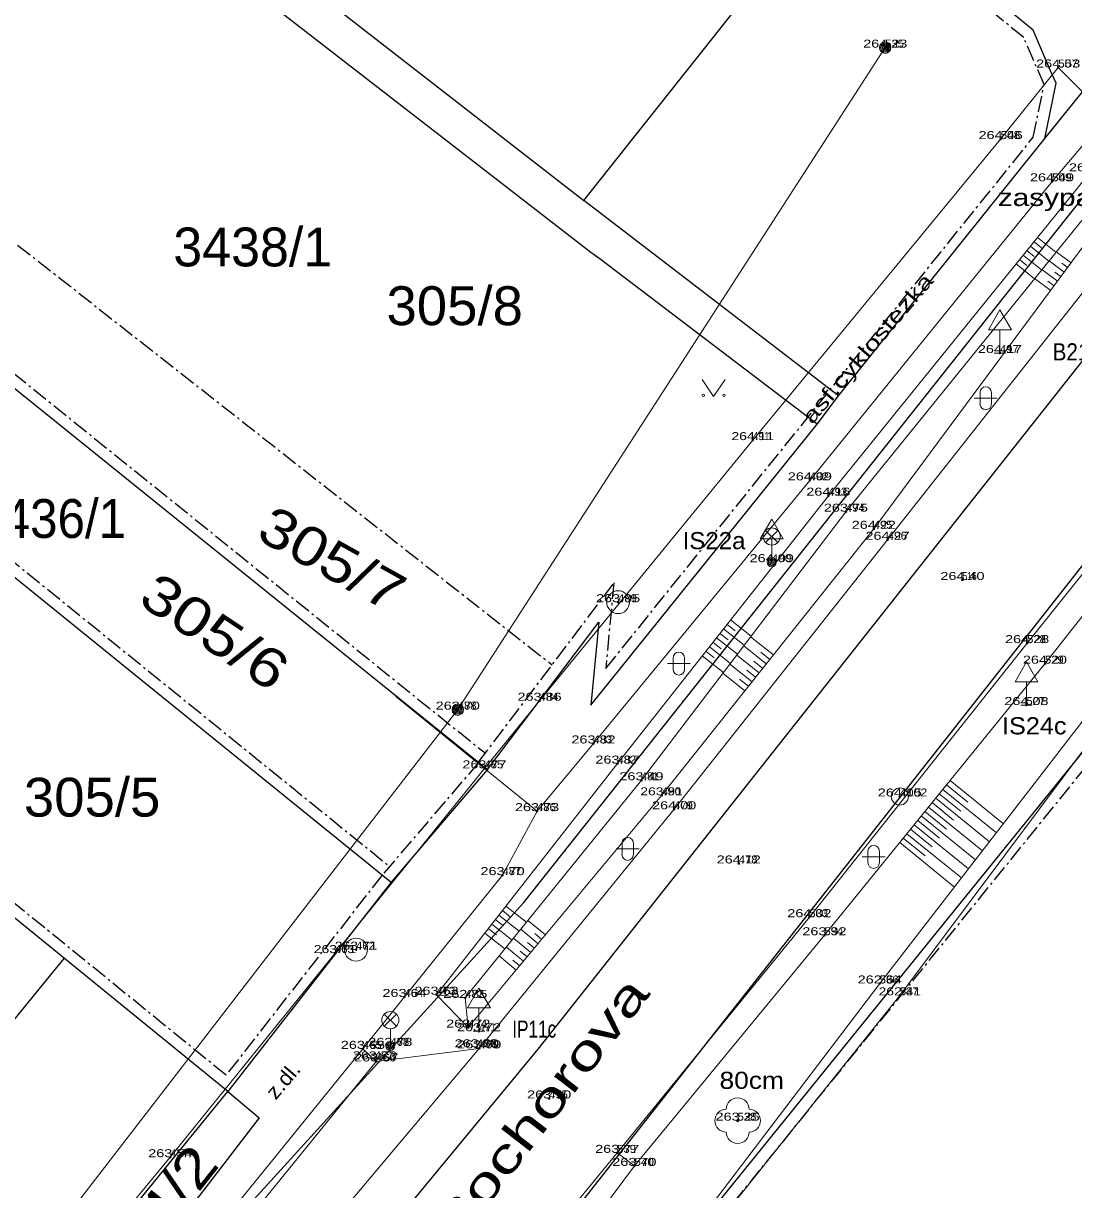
# Model space of a CAD drawing. Extents: x -568530 to -568223, y -1154101 to -1153740.
# Drawn here: x -568404.2 to -568358.2, y -1153886.3 to -1153835.3 of the extents above; entities that cross this region are included whole.
import ezdxf
from ezdxf.enums import TextEntityAlignment as Align

# ---------------------------------------------------------------- set-up
doc = ezdxf.new("R2010")
doc.units = 0
doc.header["$LTSCALE"] = 0.14
doc.header["$PDMODE"] = 32
doc.header["$PDSIZE"] = 0.07
doc.linetypes.add('DOT_DASHED', pattern=[7.7, 5, -1.2, 0.3, -1.2])
for name, color, linetype, lineweight in [('1', 7, 'Continuous', 25), ('10', 7, 'Continuous', 13), ('11', 7, 'Continuous', 13), ('12', 7, 'Continuous', 13), ('14', 7, 'Continuous', 13), ('15', 7, 'Continuous', 13), ('21', 7, 'Continuous', 13), ('22', 7, 'Continuous', 13), ('23', 7, 'Continuous', 13), ('25', 7, 'Continuous', 13), ('27', 7, 'Continuous', 13), ('33', 7, 'Continuous', 13), ('34', 7, 'Continuous', 13), ('36', 7, 'Continuous', 13), ('4', 7, 'Continuous', 25), ('42', 7, 'Continuous', 13), ('51', 7, 'Continuous', 13), ('6', 7, 'DOT_DASHED', 25), ('7', 7, 'Continuous', 13)]:
    doc.layers.add(name, color=color, linetype=linetype, lineweight=lineweight)
for name, color, linetype in [('13', 7, 'Continuous'), ('18', 7, 'Continuous'), ('20', 7, 'Continuous'), ('40', 7, 'Continuous'), ('49', 7, 'Continuous')]:
    doc.layers.add(name, color=color, linetype=linetype)

msp = doc.modelspace()

# ---------------------------------------------------------------- linework, layer by layer
at = {"layer": '1'}
for points in [[(-568412.56, -1153907.8), (-568411.98, -1153907.12), (-568411.65, -1153906.73), (-568402.04, -1153895.41), (-568393.94, -1153886.59), (-568382.28, -1153873.78), (-568334.11, -1153813.06), (-568281.93, -1153748.16)], [(-568397.85, -1153916.62), (-568348.36, -1153855.52), (-568306.73, -1153803.52), (-568266.23, -1153754.08)], [(-568359.48, -1153840.35), (-568353.42, -1153832.84), (-568366.2, -1153822.48), (-568392.31, -1153801.22), (-568392.76, -1153800.31), (-568393.76, -1153795.28)], [(-568383.87, -1153867.96), (-568379, -1153861.51), (-568379.35, -1153865.15), (-568369.44, -1153852.85), (-568368.51, -1153851.61), (-568359.48, -1153840.35), (-568358.98, -1153837.93), (-568359.22, -1153837.4), (-568359.99, -1153835.62), (-568366.98, -1153829.88), (-568367.36, -1153829.57), (-568368.31, -1153828.79), (-568387.83, -1153813.79), (-568393.04, -1153809.23)], [(-568426.4, -1153841.88), (-568423.86, -1153835.73), (-568423.37, -1153836.16), (-568412.01, -1153845.3), (-568383.87, -1153867.96), (-568388.09, -1153872.89)], [(-568431.55, -1153854.18), (-568426.4, -1153841.88), (-568388.09, -1153872.89), (-568395.23, -1153882.04)], [(-568395.23, -1153882.04), (-568406.86, -1153872.6), (-568418.87, -1153863.43), (-568431.55, -1153854.18), (-568440.41, -1153875.53)], [(-568413.73, -1153908), (-568415.28, -1153906.83), (-568404.79, -1153893.8), (-568402.87, -1153891.42), (-568401.2, -1153889.36), (-568395.23, -1153882.04), (-568393.86, -1153883.19), (-568402.8, -1153894.84), (-568404.79, -1153893.8)]]:
    msp.add_lwpolyline(points, dxfattribs=at)
msp.add_lwpolyline([(-568379.65, -1153843.07), (-568372.58, -1153834.15), (-568388.26, -1153822.12), (-568391.64, -1153826.52), (-568389.96, -1153827.98), (-568393.38, -1153832.39)], close=True, dxfattribs=at)
at = {"layer": '10'}
for points in [[(-568358.89, -1153837.25), (-568356.74, -1153839.4), (-568355.85, -1153842.56), (-568355.35, -1153843.15), (-568355.9, -1153844.67)], [(-568341.41, -1153838.94), (-568349.83, -1153849.41), (-568360.25, -1153862.43), (-568369.78, -1153874.42), (-568378.19, -1153884.73), (-568386.01, -1153894.27), (-568392.67, -1153902.27), (-568398.22, -1153909.37), (-568401.79, -1153914.15), (-568403.6, -1153916.28)], [(-568355.9, -1153844.67), (-568366.36, -1153857.91), (-568375.7, -1153869.7), (-568384.23, -1153880.16)], [(-568384.23, -1153880.16), (-568392.01, -1153889.4), (-568398.35, -1153897.64), (-568404.75, -1153905.51), (-568410.43, -1153912.49)]]:
    msp.add_lwpolyline(points, dxfattribs=at)
at = {"layer": '11'}
for p, q in [((-568381.7, -1153869.78), (-568384, -1153867.91)), ((-568388.74, -1153880.73), (-568389.32, -1153880.18)), ((-568378.19, -1153884.73), (-568377.44, -1153885.3))]:
    msp.add_line(p, q, dxfattribs=at)
for points in [[(-568358.89, -1153837.25), (-568361.41, -1153840.38), (-568372.26, -1153853.55), (-568381.59, -1153864.95), (-568384, -1153867.91)], [(-568381.7, -1153869.78), (-568379.23, -1153866.82), (-568369.76, -1153855.31), (-568359.16, -1153842.23), (-568356.74, -1153839.4)], [(-568381.7, -1153869.78), (-568383.21, -1153872.58), (-568387.5, -1153877.91), (-568389.32, -1153880.18), (-568394.71, -1153886.81), (-568401.41, -1153895.07), (-568405.07, -1153899.62), (-568408.29, -1153903.1), (-568410.38, -1153905.27)], [(-568384.23, -1153880.16), (-568388.74, -1153880.73), (-568394.35, -1153887.63), (-568400.75, -1153895.57), (-568404.48, -1153900.2), (-568404.75, -1153905.51)], [(-568377.44, -1153885.3), (-568384.74, -1153895.11), (-568391.27, -1153903.31), (-568397.56, -1153910.73)]]:
    msp.add_lwpolyline(points, dxfattribs=at)
for p in [(-568366.46, -1153836.38), (-568358.89, -1153837.25), (-568361.41, -1153840.38), (-568359.16, -1153842.23), (-568361.44, -1153849.74), (-568372.26, -1153853.55), (-568369.76, -1153855.31), (-568368.95, -1153855.98), (-568368.18, -1153856.68), (-568366.96, -1153857.43), (-568366.36, -1153857.91), (-568371.43, -1153858.89), (-568363.08, -1153859.67), (-568378.15, -1153860.64), (-568360.25, -1153862.43), (-568359.47, -1153863.33), (-568385.17, -1153865.34), (-568381.59, -1153864.95), (-568360.28, -1153865.14), (-568379.23, -1153866.82), (-568384, -1153867.91), (-568378.18, -1153867.7), (-568377.13, -1153868.43), (-568376.25, -1153869.09), (-568381.7, -1153869.78), (-568375.7, -1153869.7), (-568372.87, -1153872.07), (-568383.21, -1153872.58), (-568369.78, -1153874.42), (-568369.12, -1153875.21), (-568390.54, -1153875.99), (-568389.62, -1153875.84), (-568366.7, -1153877.32), (-568387.5, -1153877.91), (-568386.1, -1153877.81), (-568384.84, -1153877.95), (-568365.82, -1153877.84), (-568384.71, -1153879.25), (-568384.24, -1153879.41), (-568389.32, -1153880.18), (-568388.12, -1153880.05), (-568384.34, -1153880.11), (-568384.23, -1153880.16), (-568388.8, -1153880.64), (-568388.74, -1153880.73), (-568381.17, -1153882.35), (-568372.92, -1153883.32), (-568378.19, -1153884.73), (-568397.75, -1153884.92), (-568377.44, -1153885.3)]:
    msp.add_point(p, dxfattribs=at)
at = {"layer": '14'}
for points in [[(-568340.75, -1153839.71), (-568349.18, -1153850.27), (-568359.47, -1153863.33), (-568369.12, -1153875.21), (-568377.44, -1153885.3)], [(-568395.11, -1153912.31), (-568389.39, -1153905.01), (-568382.04, -1153896.57), (-568374.93, -1153888.14), (-568366.7, -1153877.32), (-568357.21, -1153865.06), (-568347.39, -1153851.22), (-568338.19, -1153841.21)], [(-568357.45, -1153841.79), (-568368.95, -1153855.98), (-568378.18, -1153867.7), (-568386.1, -1153877.81), (-568384.71, -1153879.25), (-568384.84, -1153877.95), (-568386.1, -1153877.81)], [(-568384.84, -1153877.95), (-568377.13, -1153868.43), (-568368.18, -1153856.68), (-568356.81, -1153842.64)], [(-568384.71, -1153879.25), (-568376.25, -1153869.09), (-568366.96, -1153857.43), (-568356.13, -1153842.84)]]:
    msp.add_lwpolyline(points, dxfattribs=at)
at = {"layer": '15'}
for p, q in [((-568359.948, -1153844.873), (-568359.627, -1153845.133)), ((-568359.791, -1153844.679), (-568358.988, -1153845.329)), ((-568360.421, -1153845.455), (-568359.617, -1153846.106)), ((-568360.263, -1153845.261), (-568359.942, -1153845.522)), ((-568360.106, -1153845.067), (-568359.303, -1153845.718)), ((-568358.325, -1153845.797), (-568358.975, -1153845.314)), ((-568360.735, -1153845.844), (-568359.932, -1153846.495)), ((-568360.578, -1153845.65), (-568360.257, -1153845.91)), ((-568358.623, -1153846.198), (-568359.29, -1153845.703)), ((-568358.474, -1153845.997), (-568358.737, -1153845.802)), ((-568359.219, -1153847.001), (-568359.92, -1153846.48)), ((-568358.921, -1153846.6), (-568359.605, -1153846.092)), ((-568358.772, -1153846.399), (-568359.042, -1153846.198)), ((-568359.07, -1153846.8), (-568359.347, -1153846.595)), ((-568373.538, -1153861.806), (-568372.63, -1153862.522)), ((-568373.384, -1153861.61), (-568373.021, -1153861.895)), ((-568373.229, -1153861.413), (-568372.327, -1153862.124)), ((-568373.848, -1153862.199), (-568372.933, -1153862.92)), ((-568373.693, -1153862.003), (-568373.328, -1153862.29)), ((-568371.356, -1153862.947), (-568372.35, -1153862.155)), ((-568374.312, -1153862.788), (-568373.942, -1153863.079)), ((-568374.157, -1153862.592), (-568373.236, -1153863.317)), ((-568374.002, -1153862.395), (-568373.635, -1153862.685)), ((-568371.667, -1153863.338), (-568372.653, -1153862.553)), ((-568371.512, -1153863.143), (-568371.908, -1153862.827)), ((-568374.466, -1153862.985), (-568373.539, -1153863.715)), ((-568372.291, -1153864.12), (-568373.259, -1153863.349)), ((-568371.979, -1153863.729), (-568372.956, -1153862.951)), ((-568371.823, -1153863.534), (-568372.216, -1153863.221)), ((-568372.602, -1153864.512), (-568373.562, -1153863.746)), ((-568372.135, -1153863.925), (-568372.524, -1153863.615)), ((-568372.446, -1153864.316), (-568372.832, -1153864.009)), ((-568363.62, -1153868.439), (-568361.29, -1153870.331)), ((-568363.935, -1153868.827), (-568361.596, -1153870.727)), ((-568363.778, -1153868.633), (-568362.844, -1153869.391)), ((-568364.408, -1153869.409), (-568363.467, -1153870.173)), ((-568364.25, -1153869.215), (-568361.903, -1153871.122)), ((-568364.093, -1153869.021), (-568363.155, -1153869.782)), ((-568364.881, -1153869.991), (-568362.515, -1153871.913)), ((-568364.723, -1153869.797), (-568363.779, -1153870.565)), ((-568364.566, -1153869.603), (-568362.209, -1153871.518)), ((-568365.196, -1153870.379), (-568362.821, -1153872.309)), ((-568365.039, -1153870.185), (-568364.09, -1153870.956)), ((-568365.669, -1153870.962), (-568364.713, -1153871.738)), ((-568365.511, -1153870.767), (-568363.127, -1153872.704)), ((-568365.354, -1153870.573), (-568364.402, -1153871.347)), ((-568365.827, -1153871.156), (-568363.433, -1153873.1)), ((-568383.064, -1153873.935), (-568382.161, -1153874.642)), ((-568383.527, -1153874.525), (-568383.169, -1153874.805)), ((-568383.372, -1153874.328), (-568382.476, -1153875.031)), ((-568383.218, -1153874.131), (-568382.858, -1153874.413)), ((-568381.335, -1153875.197), (-568382.097, -1153874.563)), ((-568383.835, -1153874.919), (-568383.48, -1153875.197)), ((-568383.681, -1153874.722), (-568382.791, -1153875.419)), ((-568381.655, -1153875.581), (-568382.412, -1153874.951)), ((-568383.989, -1153875.116), (-568383.105, -1153875.808)), ((-568381.975, -1153875.966), (-568382.726, -1153875.34)), ((-568381.815, -1153875.773), (-568382.117, -1153875.522)), ((-568381.495, -1153875.389), (-568381.799, -1153875.136)), ((-568382.615, -1153876.734), (-568383.356, -1153876.117)), ((-568382.295, -1153876.35), (-568383.041, -1153875.729)), ((-568382.135, -1153876.158), (-568382.435, -1153875.908)), ((-568382.455, -1153876.542), (-568382.752, -1153876.294))]:
    msp.add_line(p, q, dxfattribs=at)
at = {"layer": '21'}
for radius in [0.375, 0.05]:
    msp.add_circle((-568365.82, -1153869.14), radius, dxfattribs=at)
at = {"layer": '22'}
msp.add_circle((-568372.92, -1153883.32), 0.05, dxfattribs=at)
for centre, start, end in [((-568372.92, -1153882.82), 0, 180), ((-568373.42, -1153883.32), 90, 270), ((-568372.42, -1153883.32), 270, 90), ((-568372.92, -1153883.82), 180, 0)]:
    msp.add_arc(centre, 0.5, start, end, dxfattribs=at)
at = {"layer": '23'}
msp.add_lwpolyline([(-568354.04, -1153929.41), (-568364.61, -1153923.44), (-568379.16, -1153915.86), (-568390.37, -1153909.46), (-568387.81, -1153906.15), (-568381.36, -1153897.16), (-568374.28, -1153888.42), (-568365.82, -1153877.84), (-568356.68, -1153865.62), (-568346.38, -1153852.31), (-568338.19, -1153841.21)], dxfattribs=at)
at = {"layer": '25'}
for centre, radius in [((-568366.46, -1153836.38), 0.25), ((-568366.46, -1153836.38), 0.2), ((-568366.46, -1153836.38), 0.15), ((-568366.46, -1153836.38), 0.1), ((-568366.46, -1153836.38), 0.05), ((-568385.17, -1153865.34), 0.25), ((-568385.17, -1153865.34), 0.2), ((-568385.17, -1153865.34), 0.15), ((-568385.17, -1153865.34), 0.1), ((-568385.17, -1153865.34), 0.05)]:
    msp.add_circle(centre, radius, dxfattribs=at)
at = {"layer": '27'}
for centre in [(-568378.15, -1153860.64), (-568389.62, -1153875.84)]:
    msp.add_circle(centre, 0.5, dxfattribs=at)
at = {"layer": '33'}
for p, q in [((-568371.695, -1153858.03), (-568371.165, -1153857.5)), ((-568371.695, -1153857.5), (-568371.165, -1153858.03)), ((-568371.43, -1153858.14), (-568371.43, -1153858.89)), ((-568388.385, -1153879.19), (-568387.855, -1153878.66)), ((-568388.385, -1153878.66), (-568387.855, -1153879.19)), ((-568388.12, -1153879.3), (-568388.12, -1153880.05))]:
    msp.add_line(p, q, dxfattribs=at)
for centre, radius in [((-568371.43, -1153857.765), 0.375), ((-568371.43, -1153858.89), 0.2), ((-568371.43, -1153858.89), 0.1445), ((-568371.43, -1153858.89), 0.0876), ((-568388.12, -1153878.925), 0.375), ((-568388.12, -1153880.05), 0.2), ((-568388.12, -1153880.05), 0.1445), ((-568388.12, -1153880.05), 0.0876)]:
    msp.add_circle(centre, radius, dxfattribs=at)
at = {"layer": '34'}
for p, q in [((-568361.44, -1153848.722), (-568361.44, -1153849.74)), ((-568361.69, -1153849.74), (-568361.19, -1153849.74)), ((-568371.43, -1153857.872), (-568371.43, -1153858.89)), ((-568360.28, -1153864.122), (-568360.28, -1153865.14)), ((-568360.53, -1153865.14), (-568360.03, -1153865.14)), ((-568384.24, -1153878.392), (-568384.24, -1153879.41)), ((-568384.49, -1153879.41), (-568383.99, -1153879.41))]:
    msp.add_line(p, q, dxfattribs=at)
for points in [[(-568361.94, -1153848.722), (-568360.94, -1153848.722), (-568361.44, -1153847.856)], [(-568371.93, -1153857.872), (-568370.93, -1153857.872), (-568371.43, -1153857.006)], [(-568360.78, -1153864.122), (-568359.78, -1153864.122), (-568360.28, -1153863.256)], [(-568384.74, -1153878.392), (-568383.74, -1153878.392), (-568384.24, -1153877.526)]]:
    msp.add_lwpolyline(points, close=True, dxfattribs=at)
at = {"layer": '36'}
for p, q in [((-568362.312, -1153851.467), (-568362.312, -1153851.967)), ((-568361.812, -1153851.467), (-568361.812, -1153851.967)), ((-568362.562, -1153851.717), (-568361.562, -1153851.717)), ((-568375.992, -1153863.325), (-568374.992, -1153863.325)), ((-568375.742, -1153863.075), (-568375.742, -1153863.575)), ((-568375.242, -1153863.075), (-568375.242, -1153863.575)), ((-568378.231, -1153871.431), (-568377.231, -1153871.431)), ((-568377.981, -1153871.181), (-568377.981, -1153871.681)), ((-568377.481, -1153871.181), (-568377.481, -1153871.681)), ((-568367.465, -1153871.782), (-568366.465, -1153871.782)), ((-568367.215, -1153871.532), (-568367.215, -1153872.032)), ((-568366.715, -1153871.532), (-568366.715, -1153872.032))]:
    msp.add_line(p, q, dxfattribs=at)
msp.add_lwpolyline([(-568374.47, -1153850.893), (-568373.97, -1153851.643), (-568373.47, -1153850.893)], dxfattribs=at)
for centre in [(-568374.4206, -1153851.5927), (-568373.5212, -1153851.5927)]:
    msp.add_circle(centre, 0.05, dxfattribs=at)
for centre, start, end in [((-568362.0622, -1153851.4692), 0, 180), ((-568362.0622, -1153851.9692), 180, 0), ((-568375.4922, -1153863.0771), 0, 180), ((-568375.4922, -1153863.5771), 180, 0), ((-568377.7315, -1153871.1828), 0, 180), ((-568366.9648, -1153871.534), 0, 180), ((-568377.7315, -1153871.6828), 180, 0), ((-568366.9648, -1153872.034), 180, 0)]:
    msp.add_arc(centre, 0.25, start, end, dxfattribs=at)
at = {"layer": '4'}
msp.add_line((-568368.51, -1153851.61), (-568379.65, -1153843.07), dxfattribs=at)
for points in [[(-568271.05, -1153741.89), (-568310.68, -1153791.16), (-568343.12, -1153831.47), (-568381.67, -1153880.2), (-568407.5, -1153911.44)], [(-568401.59, -1153914.63), (-568397.99, -1153910.05), (-568332.4, -1153826.72), (-568306.48, -1153794.28), (-568270.78, -1153751.53)], [(-568369.44, -1153852.85), (-568378.94, -1153845.64), (-568379.34, -1153845.34), (-568413.29, -1153819.07)], [(-568422.9, -1153878.41), (-568413.58, -1153883.34), (-568414.1, -1153884.23), (-568410.52, -1153886.17), (-568402.39, -1153876.23)]]:
    msp.add_lwpolyline(points, dxfattribs=at)
at = {"layer": '51'}
msp.add_lwpolyline([(-568408.38, -1153895.39), (-568385.17, -1153865.34), (-568366.46, -1153836.38)], dxfattribs=at)
at = {"layer": '6'}
for p, q in [((-568360.4, -1153835.94), (-568367.3, -1153830.27)), ((-568359.51, -1153838), (-568360.4, -1153835.94)), ((-568413.37, -1153838), (-568381.04, -1153863.38)), ((-568359.98, -1153840.3), (-568359.51, -1153838.01)), ((-568378.69, -1153863.54), (-568359.98, -1153840.3)), ((-568426.09, -1153841.49), (-568388.15, -1153872.2)), ((-568411.7, -1153844.91), (-568383.96, -1153867.25)), ((-568390.25, -1153908.12), (-568347.97, -1153855.84)), ((-568384.27, -1153867.66), (-568378.34, -1153859.81)), ((-568378.34, -1153859.8), (-568378.69, -1153863.54)), ((-568384.25, -1153867.64), (-568388.47, -1153872.57)), ((-568395.31, -1153881.33), (-568406.55, -1153872.21)), ((-568388.48, -1153872.58), (-568395.31, -1153881.33))]:
    msp.add_line(p, q, dxfattribs=at)
at = {"layer": '7'}
msp.add_line((-568387.886, -1153864.764), (-568384, -1153867.91), dxfattribs=at)
msp.add_lwpolyline([(-568384, -1153867.91), (-568390.54, -1153875.99), (-568397.75, -1153884.92), (-568401.83, -1153889.84)], dxfattribs=at)

# ---------------------------------------------------------------- texts
at = {"layer": '12'}
for s, width, p in [('264.23', 1.35, (-568366.46, -1153836.38)), ('264.53', 1.35, (-568358.89, -1153837.25)), ('264.46', 1.35, (-568361.41, -1153840.38)), ('264.49', 1.35, (-568359.16, -1153842.23)), ('264.49', 1.35, (-568357.45, -1153841.79)), ('264.17', 1.35, (-568361.44, -1153849.74)), ('264.11', 1.3, (-568372.26, -1153853.55)), ('264.09', 1.35, (-568369.76, -1153855.31)), ('264.16', 1.35, (-568368.95, -1153855.98)), ('263.75', 1.35, (-568368.1805, -1153856.68)), ('264.22', 1.35, (-568366.96, -1153857.43)), ('264.27', 1.35, (-568366.36, -1153857.91)), ('264.09', 1.35, (-568371.43, -1153858.89)), ('264.40', 1.35, (-568363.0795, -1153859.67)), ('263.95', 1.35, (-568378.1505, -1153860.64)), ('264.28', 1.35, (-568360.25, -1153862.43)), ('264.20', 1.35, (-568359.4695, -1153863.33)), ('263.86', 1.35, (-568381.59, -1153864.95)), ('264.08', 1.35, (-568360.28, -1153865.14)), ('263.70', 1.35, (-568385.1695, -1153865.34)), ('263.82', 1.35, (-568379.23, -1153866.82)), ('263.87', 1.35, (-568378.18, -1153867.7)), ('263.77', 1.35, (-568384, -1153867.91)), ('263.49', 1.35, (-568377.13, -1153868.43)), ('263.91', 1.3, (-568376.25, -1153869.09)), ('263.73', 1.35, (-568381.7, -1153869.78)), ('264.00', 1.35, (-568375.6995, -1153869.7)), ('264.12', 1.35, (-568372.87, -1153872.07)), ('263.70', 1.35, (-568383.2095, -1153872.58)), ('264.02', 1.35, (-568369.78, -1153874.42)), ('263.92', 1.35, (-568369.12, -1153875.21)), ('263.71', 1.3, (-568389.62, -1153875.84)), ('263.71', 1.3, (-568390.54, -1153875.99)), ('262.64', 1.35, (-568366.7, -1153877.32)), ('263.64', 1.35, (-568387.5, -1153877.91)), ('263.63', 1.35, (-568386.1, -1153877.81)), ('262.85', 1.35, (-568384.8405, -1153877.95)), ('262.41', 1.3, (-568365.82, -1153877.84)), ('263.72', 1.35, (-568384.71, -1153879.25)), ('263.72', 1.35, (-568384.24, -1153879.41)), ('263.65', 1.35, (-568389.3205, -1153880.18)), ('263.78', 1.35, (-568388.12, -1153880.05)), ('263.80', 1.35, (-568384.3395, -1153880.11)), ('263.79', 1.35, (-568384.23, -1153880.16)), ('263.73', 1.35, (-568388.8, -1153880.64)), ('263.67', 1.35, (-568388.74, -1153880.73)), ('263.90', 1.35, (-568381.1695, -1153882.35)), ('263.25', 1.35, (-568372.9205, -1153883.32)), ('263.54', 1.35, (-568397.75, -1153884.92)), ('263.77', 1.35, (-568378.19, -1153884.73)), ('263.70', 1.35, (-568377.4395, -1153885.3))]:
    msp.add_text(s, height=0.35, dxfattribs=dict(at, width=width)).set_placement(p, align=Align.CENTER)
at = {"layer": '13'}
for s, width, p in [('535', 1.05, (-568366.46, -1153836.38)), ('507', 1.1, (-568358.89, -1153837.25)), ('508', 1.1, (-568361.41, -1153840.38)), ('509', 1.1, (-568359.16, -1153842.23)), ('497', 1.05, (-568361.44, -1153849.74)), ('491', 0.95, (-568372.26, -1153853.55)), ('492', 1.05, (-568369.76, -1153855.31)), ('493', 1.05, (-568368.95, -1153855.98)), ('494', 1.05, (-568368.18, -1153856.68)), ('495', 1.05, (-568366.96, -1153857.43)), ('496', 1.1, (-568366.36, -1153857.91)), ('490', 1.1, (-568371.43, -1153858.89)), ('516', 0.8, (-568363.08, -1153859.67)), ('489', 1.05, (-568378.15, -1153860.64)), ('528', 1.05, (-568360.25, -1153862.43)), ('529', 1.05, (-568359.47, -1153863.33)), ('484', 1.05, (-568381.59, -1153864.95)), ('527', 1.05, (-568360.28, -1153865.14)), ('488', 1.05, (-568385.17, -1153865.34)), ('483', 1.05, (-568379.23, -1153866.82)), ('482', 1.05, (-568378.18, -1153867.7)), ('485', 1.05, (-568384, -1153867.91)), ('481', 0.95, (-568377.13, -1153868.43)), ('480', 1.1, (-568376.25, -1153869.09)), ('486', 1.05, (-568381.7, -1153869.78)), ('479', 1.05, (-568375.7, -1153869.7)), ('478', 1.05, (-568372.87, -1153872.07)), ('487', 1.05, (-568383.21, -1153872.58)), ('533', 1.05, (-568369.78, -1153874.42)), ('534', 1.05, (-568369.12, -1153875.21)), ('462', 1.05, (-568389.62, -1153875.84)), ('463', 1.05, (-568390.54, -1153875.99)), ('536', 1.05, (-568366.7, -1153877.32)), ('464', 1.05, (-568387.5, -1153877.91)), ('473', 1.05, (-568386.1, -1153877.81)), ('472', 1.05, (-568384.84, -1153877.95)), ('537', 1.05, (-568365.82, -1153877.84)), ('474', 1.05, (-568384.71, -1153879.25)), ('471', 0.95, (-568384.24, -1153879.41)), ('465', 1.05, (-568389.32, -1153880.18)), ('468', 1.05, (-568388.12, -1153880.05)), ('470', 1.1, (-568384.34, -1153880.11)), ('469', 1.1, (-568384.23, -1153880.16)), ('467', 1.05, (-568388.8, -1153880.64)), ('466', 1.1, (-568388.74, -1153880.73)), ('475', 1.05, (-568381.17, -1153882.35)), ('538', 1.05, (-568372.92, -1153883.32)), ('457', 1.05, (-568397.75, -1153884.92)), ('539', 1.05, (-568378.19, -1153884.73)), ('540', 1.1, (-568377.44, -1153885.3))]:
    msp.add_text(s, height=0.35, dxfattribs=dict(at, width=width)).set_placement(p)
at = {"layer": '18'}
msp.add_text('3438/1', height=1.7, dxfattribs=at).set_placement((-568397.62, -1153845.95))
at = {"layer": '18', "width": 0.95}
msp.add_text('3436/1', height=1.7, dxfattribs=at).set_placement((-568406.29, -1153857.83))
at = {"layer": '18', "width": 1.25}
msp.add_text('3434/2', height=1.7, rotation=51.6, dxfattribs=at).set_placement((-568400.952, -1153892.08))
at = {"layer": '20', "width": 1.05}
for s, p in [('305/8', (-568388.29, -1153848.52)), ('305/5', (-568404.16, -1153870.02))]:
    msp.add_text(s, height=1.7, dxfattribs=at).set_placement(p)
at = {"layer": '20'}
for s, rotation, width, p in [('305/7', 330.911, 1.2, (-568394.062, -1153857.827)), ('305/6', 326.35, 1.25, (-568399.23, -1153860.666))]:
    msp.add_text(s, height=1.7, rotation=rotation, dxfattribs=dict(at, width=width)).set_placement(p)
at = {"layer": '22', "width": 1.35}
msp.add_text('264.15', height=0.35, dxfattribs=at).set_placement((-568365.8205, -1153869.14), align=Align.CENTER)
at = {"layer": '23', "width": 1.15}
msp.add_text('4002', height=0.35, dxfattribs=at).set_placement((-568365.82, -1153869.14))
at = {"layer": '40'}
for s, width, p in [('asf.cyklostezka', 1.4, (-568369.662, -1153852.89)), ('z.dl.', 1.1, (-568393.137, -1153882.443))]:
    msp.add_text(s, height=0.65, rotation=49.573, dxfattribs=dict(at, width=width)).set_placement(p)
at = {"layer": '42'}
for s, width, p in [('zasypano', 1.3, (-568358.7435, -1153843.307)), ('B21a', 0.9, (-568358.0795, -1153850.064)), ('IS22a', 1.05, (-568373.952, -1153858.322)), ('IS24c', 1.1, (-568359.938, -1153866.422)), ('IP11c', 0.75, (-568381.822, -1153879.69)), ('80cm', 1.15, (-568372.303, -1153881.931))]:
    msp.add_text(s, height=0.75, dxfattribs=dict(at, width=width)).set_placement(p, align=Align.CENTER)
at = {"layer": '49', "width": 1.45}
msp.add_text('Sochorova', height=1.5, rotation=52.355, dxfattribs=at).set_placement((-568385.198, -1153888.782))

doc.saveas('drawing.dxf')
